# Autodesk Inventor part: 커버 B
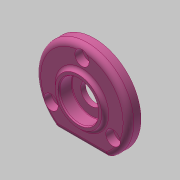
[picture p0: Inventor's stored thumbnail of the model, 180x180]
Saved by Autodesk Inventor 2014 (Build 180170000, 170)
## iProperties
Created: 2020-04
Part Number: 커버 B
Material: 알루미늄 6061
Document SubType Name: Modeling
Designer: mduedu
Density: 2.71 g/cm^3
Appearance: 분홍색
Mass: 33.6764 g
Surface Area: 62.2842 cm^2
Volume: 12.4267 cm^3
Author: mduedu
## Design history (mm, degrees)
sketch "스케치1"
  geometry: C1 r 26 at (0, 0); 1 further point
  constraints: 1 centre point, 1 coincident
  dimensions: "d0" = 52 diameter of C1
extrude "돌출1" new body sketch "스케치1" distance "d1" = 7; taper "d2" = 0 deg
sketch "스케치2"
  geometry: L1 (-14.62, -21.5)-(14.62, -21.5); A1 r 26 centre (0, 0) between (-14.62, -21.5) and (14.62, -21.5) reference; 1 further point
  constraints: 2 end point, 2 point on circle, 1 horizontal
  dimensions: "d3" = 21.5 distance from line of L1 point (0, 0)
extrude "돌출2" cut sketch "스케치2" stored distance "d4" = 7; taper "d5" = 0 deg
sketch "스케치6"
  geometry: C1 r 13 at (0, 0); 1 further point
  constraints: 1 centre point, 1 coincident
  dimensions: "d29" = 26 diameter of C1
extrude "돌출5" join sketch "스케치6" distance "d30" = 2; taper "d31" = 0 deg
fillet "모깎기1" dims "d6" = 3
fillet "모깎기2" dims "d7" = 3
fillet "모깎기4" dims "d33" = 2
sketch "스케치3" dims "d8" = 40
  geometry: 3 further points
  constraints: 2 vertical alignment, 1 coincident, 2 other
hole "구멍1" sketch "스케치3" at (0, 20) diameter "d9" = 4.5; stored, may be unused: countersink angle "d13" = 90 deg, drill point angle "d15" = 118 deg; dims "d10" = 6, "d11" = 8, "d12" = 4.4, "d14" = 8
sketch "스케치4"
  geometry: C1 r 14 at (0, 0); 1 further point
  constraints: 1 centre point, 1 coincident
  dimensions: "d19" = 28 diameter of C1
extrude "돌출3" join sketch "스케치4" distance "d20" = 4; taper "d21" = 0 deg
sketch "스케치5"
  geometry: C1 r 12 at (0, 0); 1 further point
  constraints: 1 centre point, 1 coincident
  dimensions: "d22" = 24 diameter of C1
extrude "돌출4" cut sketch "스케치5" distance "d23" = 3; taper "d24" = 0 deg
fillet "모깎기3" dims "d25" = 3
chamfer "모따기1" distance "d26" = 0.5; stored, may be unused: second distance "d27" = 2, angle "d28" = 45 deg
sketch "스케치7"
  geometry: 2 further points
  constraints: 1 coincident
hole "구멍2" sketch "스케치7" at (0, 0) diameter "d34" = 12; stored, may be unused: countersink angle "d38" = 90 deg, drill point angle "d40" = 118 deg; dims "d35" = 6, "d36" = 22, "d37" = 7.3, "d39" = 8
fillet "모깎기5" dims "d41" = 0.3
chamfer "모따기2" distance "d42" = 0.7; stored, may be unused: second distance "d43" = 2, angle "d44" = 30 deg
node "솔리드1"
pattern_circular "원형 패턴1" dims angle "d17" = 360 deg
node "투영된 루프1"
